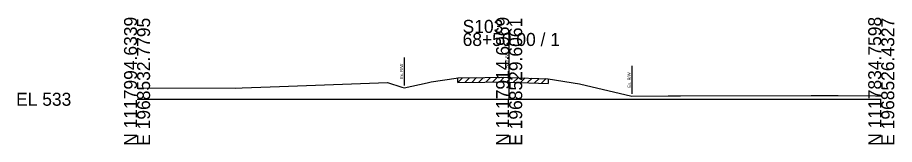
# Model space of a CAD drawing. Extents: x -26 to 163, y -10 to 24018.
# Drawn here: x -25.7 to 162.8, y 16490.3 to 16517.5 of the extents above; entities that cross this region are included whole.
import ezdxf

# ---------------------------------------------------------------- set-up
doc = ezdxf.new("R2010")
doc.units = 0
for name, color, linetype in [('RD_GPK_XS_Cell', 7, 'Continuous'), ('RD_XS_ExGround', 7, 'Continuous'), ('RD_XS_ExPaveRet', 7, 'Continuous'), ('RD_XS_ExRW', 7, 'Continuous'), ('RD_XS_TX_Elev_EX', 7, 'Continuous')]:
    doc.layers.add(name, color=color, linetype=linetype)

msp = doc.modelspace()

# ---------------------------------------------------------------- linework, layer by layer
at = {"layer": 'RD_GPK_XS_Cell'}
for p, q in [((80, 16500), (80, 16514.23)), ((0, 16500), (80, 16500)), ((80, 16500), (160, 16500))]:
    msp.add_line(p, q, dxfattribs=at)
at = {"layer": 'RD_XS_ExGround'}
msp.add_lwpolyline([(0, 16502.45), (21.11, 16502.4), (22.61, 16502.46), (30.6, 16502.76), (53.84, 16503.63), (56.94, 16502.63), (57.45, 16502.48), (62.41, 16503.54), (63.23, 16503.71), (68.62, 16504.53), (68.97, 16504.58), (74.8, 16504.68), (78.41, 16504.74), (80, 16504.69), (88.37, 16504.41), (95.11, 16503.32), (106.36, 16500.64), (114.19, 16500.7), (116.83, 16500.7), (144.92, 16500.79), (150.74, 16500.78), (158.78, 16500.7), (160, 16500.69)], dxfattribs=at)
at = {"layer": 'RD_XS_ExPaveRet'}
for p, q in [((68.97, 16503.58), (69.99, 16504.6)), ((68.97, 16503.58), (68.97, 16504.58)), ((70.47, 16503.61), (71.49, 16504.62)), ((71.97, 16503.63), (72.99, 16504.65)), ((73.47, 16503.66), (74.49, 16504.67)), ((74.97, 16503.68), (75.99, 16504.7)), ((76.47, 16503.71), (77.49, 16504.73)), ((77.97, 16503.74), (78.96, 16504.72)), ((79.47, 16503.71), (80.44, 16504.68)), ((80.97, 16503.66), (81.94, 16504.63)), ((82.47, 16503.61), (83.44, 16504.58)), ((83.97, 16503.56), (84.94, 16504.53)), ((85.47, 16503.51), (86.44, 16504.48)), ((86.97, 16503.46), (87.94, 16504.43)), ((88.37, 16504.41), (88.37, 16503.41)), ((68.97, 16503.58), (74.8, 16503.68)), ((74.8, 16503.68), (78.41, 16503.74)), ((78.41, 16503.74), (80, 16503.69)), ((80, 16503.69), (88.37, 16503.41))]:
    msp.add_line(p, q, dxfattribs=at)
at = {"layer": 'RD_XS_ExRW'}
for p, q in [((57.45, 16508.98), (57.45, 16502.98)), ((106.36, 16507.14), (106.36, 16501.14))]:
    msp.add_line(p, q, dxfattribs=at)

# ---------------------------------------------------------------- texts
at = {"layer": 'RD_GPK_XS_Cell'}
for s, p in [('N 1117994.6339', (0, 16490)), ('N 1117914.6969', (80, 16490)), ('N 1117834.7598', (160, 16490)), ('E 1968532.7795', (2.8, 16490)), ('E 1968529.6061', (82.8, 16490)), ('E 1968526.4327', (162.8, 16490))]:
    msp.add_text(s, height=2.8, rotation=90, dxfattribs=at).set_placement(p)
for s, p in [('S103', (70, 16514.23)), ('68+50.00 / 1', (70, 16511.43)), ('EL 533', (-26, 16498.6))]:
    msp.add_text(s, height=2.8, dxfattribs=at).set_placement(p)
at = {"layer": 'RD_XS_ExRW'}
for p in [(57.2, 16504.32), (106.11, 16502.48)]:
    msp.add_text('Ex. R/W ', height=0.65, rotation=90, dxfattribs=at).set_placement(p)
at = {"layer": 'RD_XS_TX_Elev_EX'}
msp.add_text('537.69', height=0.8, rotation=90, dxfattribs=at).set_placement((79.9, 16506.69))

doc.saveas('drawing.dxf')
